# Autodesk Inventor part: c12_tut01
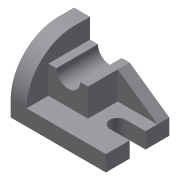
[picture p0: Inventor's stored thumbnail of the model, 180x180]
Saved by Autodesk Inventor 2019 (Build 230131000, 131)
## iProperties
Shininess: 77.0
Length Units: 11269
Angle Units: 11279
Time Units: 11290
Mass Units: 11283
Length Display Precision: 3
Angle Display Precision: 2
Created: 2001-11
Part Number: c12_tut01
Document SubType Name: Modeling
Designer: Renu Muthoo
Density: 1 g/cm^3
Material: Generic
Appearance: Default
Density: 0.0
Volumn: 0.0
Area: 0.0
PropertySet Name: Model Information
Control State: 0
Master: False
Checked Out: False
Author: Renu Muthoo
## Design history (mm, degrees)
sketch "Sketch1"
  geometry: L1 (-48, 36)-(48, 36); L2 (48, -28)-(-48, -28); L3 (-48, -28)-(-48, 36); L4 (48, 12)-(28, 12); L5 (28, -4)-(48, -4); L6 (48, 36)-(48, 12); L7 (48, -4)-(48, -28); A1 r 8 centre (28, 4) between (28, 12) and (28, -4)
  constraints: 14 end point, 4 parallel, 3 perpendicular, 2 point on circle, 2 tangent, 1 centre point, 1 collinear, 1 horizontal
  dimensions: "d0" = 96 distance of L2.start L2.end; "d1" = 64 distance of L2.end L1.start; "d2" = 20 distance of L4.start L4.end; "d3" = 24 distance between parallel lines of L2 L5; "d4" = 16 distance between parallel lines of L4 L5
extrude "Extrusion1" new body sketch "Sketch1" distance "d5" = 16; taper "d6" = 0 deg
sketch "Sketch2"
  geometry: L1 (16, 64)-(64, 64); L2 (64, 64)-(64, 48); L3 (16, 0)-(16, 0); L4 (16, 0)-(16, 64); L5 (0, 64)-(16, 64) reference; L6 (16, 0)-(16, 64) reference; L7 (0, 0)-(16, 0) reference; L8 (0, 0)-(0, 64) reference; A1 r 48 centre (16, 48) between (16, 0) and (64, 48)
  constraints: 8 end point, 3 collinear, 3 perpendicular, 2 point on circle, 2 tangent, 1 centre point, 1 horizontal
  dimensions: "d7" = 64 distance between parallel lines of L2 L8; "d8" = 48 radius of A1
extrude "Extrusion2" join sketch "Sketch2" distance "d9" = 16; taper "d10" = 0 deg
sketch "Sketch3"
  geometry: L1 (16, -44)-(16, -16); L2 (16, -16)-(56, -16); L3 (56, -16)-(56, -44); L4 (56, -44)-(48, -44); L5 (24, -44)-(16, -44); L6 (16, -64)-(16, -16) reference; L7 (16, -16)-(96, -16) reference; A1 r 12 centre (36, -44) between (48, -44) and (24, -44)
  constraints: 10 end point, 3 collinear, 3 parallel, 2 equal length, 2 point on circle, 1 centre point, 1 perpendicular, 1 point on line, 1 vertical
  dimensions: "d11" = 28 distance of L2.end L3.end; "d12" = 8 distance of L3.end L4.end; "d13" = 24 distance of L5.start L4.end
extrude "Extrusion3" join sketch "Sketch3" distance "d14" = 42; taper "d15" = 0 deg
sketch "Sketch4"
  geometry: L1 (56, -16)-(96, -16) reference; L2 (56, -16)-(56, -44) reference; L3 (96, -16)-(56, -44)
  constraints: 2 end point
extrude "Extrusion4" join sketch "Sketch4" distance "d16" = 12; taper "d17" = 0 deg
body "Solid1"
